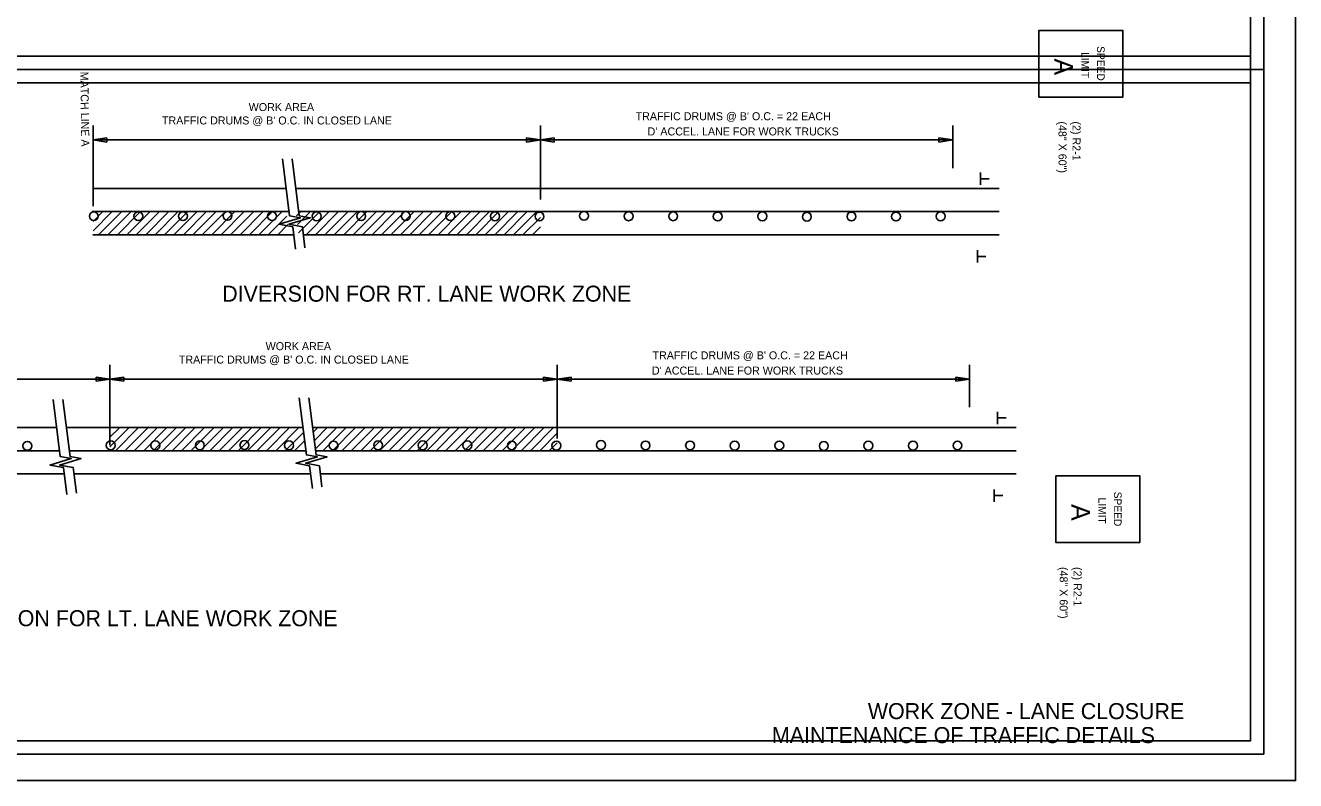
# Model space of a CAD drawing. Extents: x -500 to 213, y 382723 to 382830.
# Drawn here: x -244.8 to -149.6, y 382723.1 to 382779.8 of the extents above; entities that cross this region are included whole.
import ezdxf

# ---------------------------------------------------------------- set-up
doc = ezdxf.new("R2010")
doc.units = 0
for name, color, linetype in [('Default', 7, 'Continuous'), ('R_Border', 7, 'Continuous'), ('R_Border Plan-Plan', 7, 'Continuous'), ('R_Border Title', 7, 'Continuous'), ('R_No Plot', 7, 'Continuous')]:
    doc.layers.add(name, color=color, linetype=linetype)

msp = doc.modelspace()

# ---------------------------------------------------------------- linework, layer by layer
at = {"layer": 'Default'}
for p, q in [((-239.763, 382772.28), (-239.763, 382766.245)), ((-206.228, 382772.28), (-206.228, 382766.745)), ((-175.318, 382772.28), (-175.318, 382769.088)), ((-239.763, 382771.202), (-238.733, 382771.356)), ((-239.763, 382771.349), (-239.763, 382766.245)), ((-239.763, 382771.348), (-239.763, 382766.245)), ((-239.763, 382771.348), (-239.763, 382766.245)), ((-206.228, 382771.202), (-239.763, 382771.202)), ((-238.733, 382771.047), (-239.763, 382771.202)), ((-238.733, 382771.356), (-238.733, 382771.047)), ((-207.259, 382771.047), (-207.259, 382771.356)), ((-207.259, 382771.356), (-206.228, 382771.202)), ((-206.228, 382771.202), (-207.259, 382771.047)), ((-206.228, 382771.202), (-205.198, 382771.356)), ((-175.318, 382771.202), (-206.228, 382771.202)), ((-205.198, 382771.047), (-206.228, 382771.202)), ((-205.198, 382771.356), (-205.198, 382771.047)), ((-176.348, 382771.047), (-176.348, 382771.356)), ((-176.348, 382771.356), (-175.318, 382771.202)), ((-175.318, 382771.202), (-176.348, 382771.047)), ((-173.231, 382767.825), (-173.231, 382768.752)), ((-239.763, 382767.564), (-225.286, 382767.564)), ((-224.567, 382767.564), (-206.228, 382767.564)), ((-206.228, 382767.564), (-171.839, 382767.564)), ((-173.217, 382768.286), (-172.584, 382768.286)), ((-239.833, 382765.826), (-225.141, 382765.826)), ((-239.763, 382764.387), (-238.324, 382765.826)), ((-239.763, 382765.094), (-239.031, 382765.826)), ((-239.355, 382764.087), (-237.616, 382765.826)), ((-238.648, 382764.087), (-236.854, 382765.881)), ((-237.94, 382764.087), (-236.202, 382765.826)), ((-237.233, 382764.087), (-235.495, 382765.826)), ((-236.526, 382764.087), (-234.788, 382765.826)), ((-235.819, 382764.087), (-234.081, 382765.826)), ((-235.112, 382764.087), (-233.374, 382765.826)), ((-234.405, 382764.087), (-232.667, 382765.826)), ((-233.698, 382764.087), (-231.96, 382765.826)), ((-232.991, 382764.087), (-231.252, 382765.826)), ((-232.284, 382764.087), (-230.545, 382765.826)), ((-231.577, 382764.087), (-229.838, 382765.826)), ((-230.869, 382764.087), (-229.131, 382765.826)), ((-230.162, 382764.087), (-228.424, 382765.826)), ((-229.455, 382764.087), (-227.717, 382765.826)), ((-228.748, 382764.087), (-227.01, 382765.826)), ((-228.041, 382764.087), (-226.303, 382765.826)), ((-227.334, 382764.087), (-225.596, 382765.826)), ((-226.627, 382764.087), (-225.238, 382765.476)), ((-224.512, 382765.495), (-224.181, 382765.826)), ((-224.436, 382764.864), (-223.474, 382765.826)), ((-224.36, 382764.233), (-222.767, 382765.826)), ((-224.35, 382765.826), (-206.228, 382765.826)), ((-223.798, 382764.087), (-222.06, 382765.826)), ((-223.091, 382764.087), (-221.353, 382765.826)), ((-222.384, 382764.087), (-220.646, 382765.826)), ((-221.677, 382764.087), (-219.939, 382765.826)), ((-220.97, 382764.087), (-219.232, 382765.826)), ((-220.263, 382764.087), (-218.525, 382765.826)), ((-219.556, 382764.087), (-217.817, 382765.826)), ((-218.849, 382764.087), (-217.11, 382765.826)), ((-218.142, 382764.087), (-216.403, 382765.826)), ((-217.434, 382764.087), (-215.696, 382765.826)), ((-216.727, 382764.087), (-214.989, 382765.826)), ((-216.02, 382764.087), (-214.282, 382765.826)), ((-215.313, 382764.087), (-213.575, 382765.826)), ((-214.606, 382764.087), (-212.868, 382765.826)), ((-213.899, 382764.087), (-212.161, 382765.826)), ((-213.192, 382764.087), (-211.453, 382765.826)), ((-212.485, 382764.087), (-210.746, 382765.826)), ((-211.778, 382764.087), (-210.039, 382765.826)), ((-211.07, 382764.087), (-209.332, 382765.826)), ((-210.363, 382764.087), (-208.625, 382765.826)), ((-209.656, 382764.087), (-207.918, 382765.826)), ((-208.949, 382764.087), (-207.211, 382765.826)), ((-208.242, 382764.087), (-206.504, 382765.826)), ((-206.228, 382765.826), (-171.839, 382765.826)), ((-225.92, 382764.087), (-225.162, 382764.845)), ((-207.535, 382764.087), (-206.228, 382765.394)), ((-206.828, 382764.087), (-206.228, 382764.687)), ((-239.785, 382764.087), (-224.724, 382764.087)), ((-223.959, 382764.087), (-206.228, 382764.087)), ((-206.228, 382764.087), (-171.839, 382764.087)), ((-173.471, 382761.998), (-173.471, 382762.925)), ((-173.457, 382762.459), (-172.824, 382762.459)), ((-238.494, 382754.338), (-238.494, 382748.303)), ((-204.959, 382754.338), (-204.959, 382748.803)), ((-174.049, 382754.338), (-174.049, 382751.147)), ((-238.494, 382753.26), (-269.405, 382753.26)), ((-239.524, 382753.105), (-239.524, 382753.414)), ((-239.524, 382753.414), (-238.494, 382753.26)), ((-238.494, 382753.26), (-239.524, 382753.105)), ((-238.494, 382753.26), (-237.464, 382753.414)), ((-238.494, 382753.407), (-238.494, 382748.303)), ((-238.494, 382753.407), (-238.494, 382748.303)), ((-238.494, 382753.407), (-238.494, 382748.303)), ((-204.959, 382753.26), (-238.494, 382753.26)), ((-237.464, 382753.105), (-238.494, 382753.26)), ((-237.464, 382753.414), (-237.464, 382753.105)), ((-205.99, 382753.105), (-205.99, 382753.414)), ((-205.99, 382753.414), (-204.959, 382753.26)), ((-204.959, 382753.26), (-205.99, 382753.105)), ((-204.959, 382753.26), (-203.929, 382753.414)), ((-174.049, 382753.26), (-204.959, 382753.26)), ((-203.929, 382753.105), (-204.959, 382753.26)), ((-203.929, 382753.414), (-203.929, 382753.105)), ((-175.079, 382753.105), (-175.079, 382753.414)), ((-175.079, 382753.414), (-174.049, 382753.26)), ((-174.049, 382753.26), (-175.079, 382753.105)), ((-171.962, 382749.883), (-171.962, 382750.81)), ((-171.948, 382750.344), (-171.315, 382750.344)), ((-269.385, 382749.623), (-242.492, 382749.623)), ((-241.763, 382749.623), (-238.494, 382749.623)), ((-238.494, 382749.622), (-224.016, 382749.622)), ((-238.494, 382748.183), (-237.055, 382749.622)), ((-238.494, 382748.89), (-237.762, 382749.622)), ((-238.086, 382747.884), (-236.348, 382749.622)), ((-237.379, 382747.884), (-235.585, 382749.678)), ((-236.672, 382747.884), (-234.934, 382749.622)), ((-235.965, 382747.884), (-234.226, 382749.622)), ((-235.258, 382747.884), (-233.519, 382749.622)), ((-234.551, 382747.884), (-232.812, 382749.622)), ((-233.843, 382747.884), (-232.105, 382749.622)), ((-233.136, 382747.884), (-231.398, 382749.622)), ((-232.429, 382747.884), (-230.691, 382749.622)), ((-231.722, 382747.884), (-229.984, 382749.622)), ((-231.015, 382747.884), (-229.277, 382749.622)), ((-230.308, 382747.884), (-228.57, 382749.622)), ((-229.601, 382747.884), (-227.863, 382749.622)), ((-228.894, 382747.884), (-227.155, 382749.622)), ((-228.187, 382747.884), (-226.448, 382749.622)), ((-227.479, 382747.884), (-225.741, 382749.622)), ((-226.772, 382747.884), (-225.034, 382749.622)), ((-226.065, 382747.884), (-224.327, 382749.622)), ((-225.358, 382747.884), (-223.97, 382749.273)), ((-223.298, 382749.622), (-204.959, 382749.622)), ((-223.244, 382749.292), (-222.913, 382749.622)), ((-223.168, 382748.66), (-222.206, 382749.622)), ((-223.092, 382748.029), (-221.499, 382749.622)), ((-222.53, 382747.884), (-220.791, 382749.622)), ((-221.823, 382747.884), (-220.084, 382749.622)), ((-221.116, 382747.884), (-219.377, 382749.622)), ((-220.408, 382747.884), (-218.67, 382749.622)), ((-219.701, 382747.884), (-217.963, 382749.622)), ((-218.994, 382747.884), (-217.256, 382749.622)), ((-218.287, 382747.884), (-216.549, 382749.622)), ((-217.58, 382747.884), (-215.842, 382749.622)), ((-216.873, 382747.884), (-215.135, 382749.622)), ((-216.166, 382747.884), (-214.428, 382749.622)), ((-215.459, 382747.884), (-213.72, 382749.622)), ((-214.752, 382747.884), (-213.013, 382749.622)), ((-214.044, 382747.884), (-212.306, 382749.622)), ((-213.337, 382747.884), (-211.599, 382749.622)), ((-212.63, 382747.884), (-210.892, 382749.622)), ((-211.923, 382747.884), (-210.185, 382749.622)), ((-211.216, 382747.884), (-209.478, 382749.622)), ((-210.509, 382747.884), (-208.771, 382749.622)), ((-209.802, 382747.884), (-208.064, 382749.622)), ((-209.095, 382747.884), (-207.356, 382749.622)), ((-208.388, 382747.884), (-206.649, 382749.622)), ((-207.681, 382747.884), (-205.942, 382749.622)), ((-206.973, 382747.884), (-205.235, 382749.622)), ((-204.959, 382749.622), (-170.57, 382749.622)), ((-224.651, 382747.884), (-223.894, 382748.641)), ((-206.266, 382747.884), (-204.959, 382749.191)), ((-205.559, 382747.884), (-204.959, 382748.484)), ((-269.475, 382747.884), (-242.275, 382747.884)), ((-241.546, 382747.884), (-238.564, 382747.884)), ((-238.564, 382747.884), (-223.872, 382747.884)), ((-223.081, 382747.884), (-204.959, 382747.884)), ((-204.959, 382747.884), (-170.57, 382747.884)), ((-269.426, 382746.146), (-241.92, 382746.146)), ((-241.192, 382746.146), (-238.516, 382746.146)), ((-238.516, 382746.146), (-223.455, 382746.146)), ((-222.69, 382746.146), (-204.959, 382746.146)), ((-204.959, 382746.146), (-170.57, 382746.146)), ((-172.202, 382744.056), (-172.202, 382744.983)), ((-172.188, 382744.517), (-171.555, 382744.517))]:
    msp.add_line(p, q, dxfattribs=at)
for points in [[(-162.553, 382774.421), (-168.855, 382774.421), (-168.855, 382779.421), (-162.553, 382779.421)], [(-161.284, 382740.987), (-167.586, 382740.987), (-167.586, 382745.987), (-161.284, 382745.987)]]:
    msp.add_lwpolyline(points, close=True, dxfattribs=at)
for points in [[(-225.573, 382769.786), (-225.039, 382765.51), (-224.213, 382765.364), (-225.816, 382764.878), (-224.796, 382764.684), (-224.593, 382762.999)], [(-224.845, 382769.786), (-224.31, 382765.51), (-223.485, 382765.364), (-225.087, 382764.878), (-224.068, 382764.684), (-223.877, 382763.103)], [(-242.753, 382751.717), (-242.219, 382747.441), (-241.394, 382747.295), (-242.996, 382746.809), (-241.976, 382746.615), (-241.735, 382744.608)], [(-242.025, 382751.717), (-241.491, 382747.441), (-240.665, 382747.295), (-242.268, 382746.809), (-241.248, 382746.615), (-241.017, 382744.694)], [(-224.304, 382751.844), (-223.77, 382747.568), (-222.944, 382747.423), (-224.547, 382746.937), (-223.527, 382746.742), (-223.324, 382745.057)], [(-223.576, 382751.844), (-223.041, 382747.568), (-222.216, 382747.423), (-223.818, 382746.937), (-222.799, 382746.742), (-222.608, 382745.162)]]:
    msp.add_lwpolyline(points, dxfattribs=at)
for centre in [(-239.708, 382765.484), (-236.367, 382765.483), (-233.026, 382765.484), (-229.685, 382765.504), (-226.344, 382765.483), (-223.003, 382765.473), (-219.662, 382765.489), (-216.321, 382765.489), (-212.98, 382765.489), (-209.638, 382765.473), (-206.297, 382765.46), (-202.956, 382765.509), (-199.615, 382765.477), (-196.274, 382765.477), (-192.933, 382765.46), (-189.592, 382765.474), (-186.251, 382765.438), (-182.91, 382765.46), (-179.569, 382765.458), (-176.228, 382765.473), (-244.693, 382748.245), (-238.439, 382748.286), (-235.098, 382748.286), (-231.757, 382748.287), (-228.416, 382748.307), (-225.075, 382748.286), (-221.734, 382748.275), (-218.393, 382748.291), (-215.051, 382748.291), (-211.71, 382748.291), (-208.369, 382748.275), (-205.028, 382748.263), (-201.687, 382748.311), (-198.346, 382748.279), (-195.005, 382748.279), (-191.664, 382748.263), (-188.323, 382748.276), (-184.982, 382748.241), (-181.641, 382748.263), (-178.3, 382748.26), (-174.959, 382748.276)]:
    msp.add_circle(centre, 0.333, dxfattribs=at)
at = {"layer": 'R_Border'}
for q in [(-151.99, 382827.85), (-310.08, 382725.12)]:
    msp.add_line((-151.99, 382725.12), q, dxfattribs=at)
at = {"layer": 'R_Border Plan-Plan'}
msp.add_line((-310.08, 382776.485), (-151.99, 382776.485), dxfattribs=at)
at = {"layer": 'R_No Plot'}
for points in [[(-316.283, 382829.798), (-149.613, 382829.798), (-149.613, 382723.129), (-316.283, 382723.129)], [(-152.99, 382777.485), (-309.08, 382777.485), (-309.08, 382826.85), (-184.31, 382826.85), (-184.31, 382821.91), (-175.54, 382821.91), (-163.49, 382821.91), (-163.49, 382810.744), (-152.99, 382810.744)], [(-309.08, 382826.85), (-184.31, 382826.85), (-184.31, 382821.91), (-175.54, 382821.91), (-163.49, 382821.91), (-163.49, 382810.744), (-152.99, 382810.744), (-152.99, 382726.12), (-309.08, 382726.12)], [(-309.08, 382775.485), (-152.99, 382775.485), (-152.99, 382726.12), (-309.08, 382726.12)]]:
    msp.add_lwpolyline(points, close=True, dxfattribs=at)

# ---------------------------------------------------------------- texts
at = {"layer": 'Default'}
for s, height, rotation, p in [('SPEED', 0.5729, 270, (-164.499, 382778.24)), ('A', 1.396, 270, (-167.692, 382777.312)), ('LIMIT', 0.5729, 270, (-165.67, 382777.797)), ('MATCH LINE A', 0.6, 270.80593, (-240.72, 382776.32)), ('(48" X 60")', 0.6, 270, (-167.385, 382772.592)), ('(2) R2-1', 0.6, 270, (-166.338, 382772.592)), ('SPEED', 0.5729, 270, (-163.23, 382744.806)), ('A', 1.396, 270, (-166.423, 382743.878)), ('LIMIT', 0.5729, 270, (-164.401, 382744.363)), ('(48" X 60")', 0.6, 270, (-167.302, 382739.158)), ('(2) R2-1', 0.6, 270, (-166.255, 382739.158))]:
    msp.add_text(s, height=height, rotation=rotation, dxfattribs=at).set_placement(p)
for s, height, p in [('WORK AREA', 0.6, (-228.096, 382773.37)), ("TRAFFIC DRUMS @ B' O.C. = 22 EACH", 0.6, (-199.091, 382772.681)), ("TRAFFIC DRUMS @ B' O.C. IN CLOSED LANE", 0.6, (-234.6, 382772.363)), ("D' ACCEL. LANE FOR WORK TRUCKS", 0.6, (-198.191, 382771.539)), ('DIVERSION FOR RT. LANE WORK ZONE', 1.2, (-230.082, 382759.067)), ('WORK AREA', 0.6, (-226.827, 382755.429)), ("TRAFFIC DRUMS @ B' O.C. IN CLOSED LANE", 0.6, (-233.331, 382754.421)), ("TRAFFIC DRUMS @ B' O.C. = 22 EACH", 0.6, (-197.822, 382754.74)), ("D' ACCEL. LANE FOR WORK TRUCKS", 0.6, (-197.87, 382753.597)), ('DIVERSION FOR LT. LANE WORK ZONE', 1.2, (-251.831, 382734.716))]:
    msp.add_text(s, height=height, dxfattribs=at).set_placement(p)
at = {"layer": 'R_Border Title'}
for s, p in [('WORK ZONE - LANE CLOSURE', (-181.681, 382727.745)), ('MAINTENANCE OF TRAFFIC DETAILS', (-188.87, 382725.945))]:
    msp.add_text(s, height=1.2, dxfattribs=at).set_placement(p)

doc.saveas('drawing.dxf')
